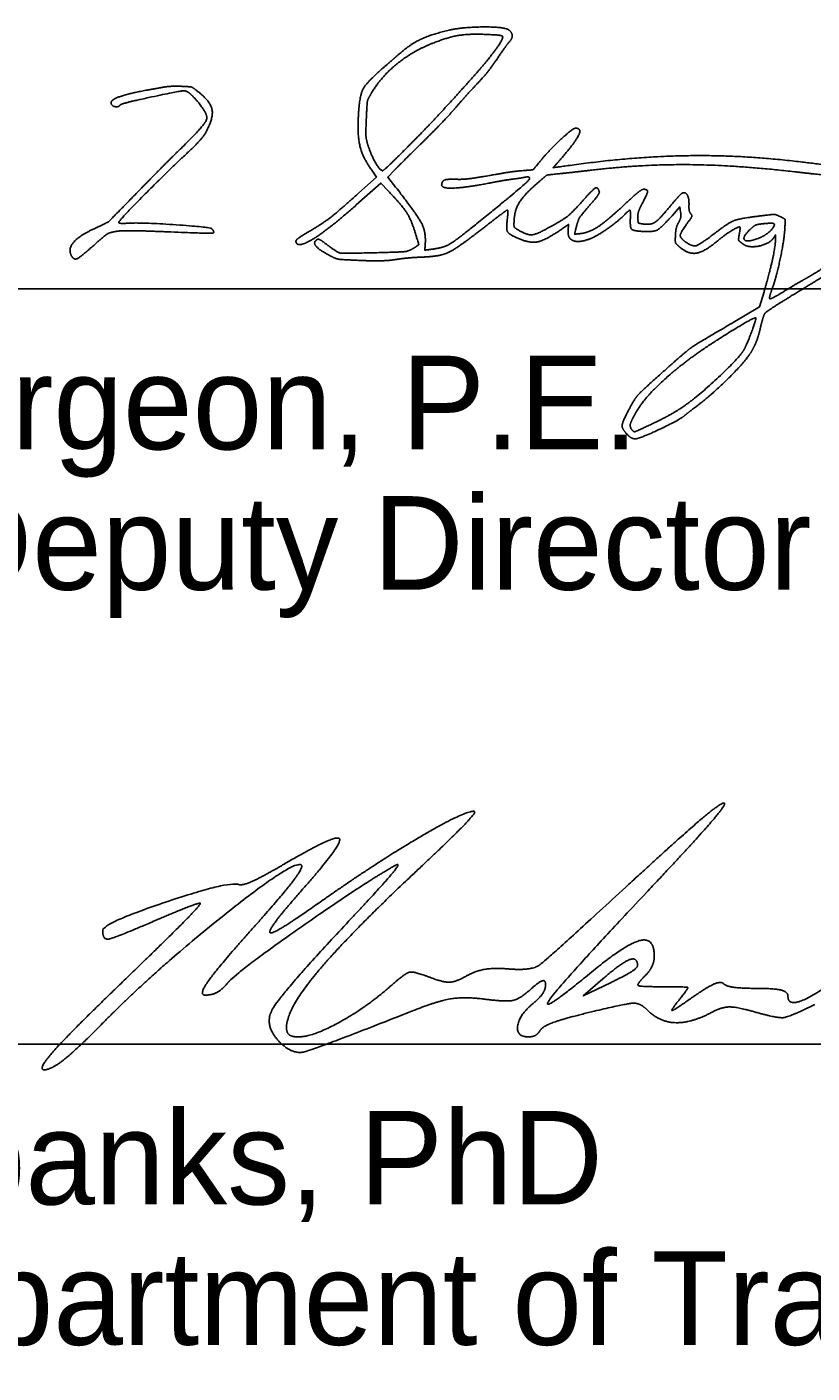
# Model space of a CAD drawing. Extents: x 0 to 34, y 0 to 22.
# Drawn here: x 25.89 to 27.065, y 8.24 to 10.253 of the extents above; entities that cross this region are included whole.
import ezdxf

# ---------------------------------------------------------------- set-up
doc = ezdxf.new("R2010")
doc.units = 0
doc.layers.add('SH_Data', color=7, linetype='Continuous')
doc.layers.add('SH_Text', color=7, linetype='Continuous')

msp = doc.modelspace()

# ---------------------------------------------------------------- linework, layer by layer
at = {"layer": 'SH_Data'}
for p, q in [((24.827, 9.8614), (28.327, 9.8614)), ((24.827, 8.7319), (28.327, 8.7319))]:
    msp.add_line(p, q, dxfattribs=at)
for points in [[(26.3868, 10.0049), (26.4132, 10.0286), (26.4051, 10.0404)], [(26.4402, 10.0391), (26.4301, 10.0287), (26.4419, 10.0136)], [(26.4309, 10.008), (26.4199, 10.0196), (26.383, 9.9869)], [(26.8681, 9.9761), (26.8668, 9.984), (26.8552, 9.9709)], [(26.7, 9.949), (26.7004, 9.9578), (26.6915, 9.9516)], [(26.9468, 9.8113), (26.986, 9.8344), (26.9928, 9.8572)]]:
    msp.add_lwpolyline(points, dxfattribs=at)
for points in [[(26.5221, 10.2484), (26.5433, 10.2532), (26.6063, 10.2532), (26.6116, 10.2484)], [(26.4976, 10.229), (26.4676, 10.2172), (26.4197, 10.1784), (26.4059, 10.1546)], [(26.4452, 10.2111), (26.4628, 10.2267), (26.4945, 10.2421), (26.5221, 10.2484)], [(26.5782, 10.242), (26.5523, 10.2431), (26.5204, 10.238), (26.4976, 10.229)], [(26.5644, 10.1861), (26.5811, 10.2051), (26.6018, 10.2335), (26.602, 10.2378)], [(26.602, 10.2378), (26.6021, 10.24), (26.5948, 10.2412), (26.5782, 10.242)], [(26.6113, 10.2302), (26.6093, 10.228), (26.6015, 10.2171), (26.594, 10.2059)], [(26.6116, 10.2484), (26.6164, 10.2442), (26.6162, 10.2355), (26.6113, 10.2302)], [(26.4267, 10.1951), (26.4344, 10.2017), (26.4427, 10.2089), (26.4452, 10.2111)], [(26.3859, 10.1149), (26.3874, 10.1493), (26.3984, 10.1708), (26.4267, 10.1951)], [(26.594, 10.2059), (26.5865, 10.1948), (26.5727, 10.1776), (26.5634, 10.1678)], [(26.4538, 10.0677), (26.4812, 10.095), (26.5305, 10.1478), (26.5644, 10.1861)], [(26.0189, 10.1439), (26.0229, 10.1474), (26.0492, 10.1549), (26.0705, 10.1588)], [(26.1436, 10.144), (26.1316, 10.1579), (26.1199, 10.1579), (26.0572, 10.1442)], [(26.0705, 10.1588), (26.0778, 10.1601), (26.0886, 10.162), (26.0944, 10.1631)], [(26.0944, 10.1631), (26.1003, 10.1641), (26.1123, 10.1647), (26.1211, 10.1644)], [(26.1211, 10.1644), (26.1347, 10.1639), (26.1386, 10.1626), (26.1474, 10.1556)], [(26.1474, 10.1556), (26.1656, 10.1412), (26.1694, 10.1158), (26.1568, 10.0935)], [(26.4059, 10.1546), (26.4001, 10.1447), (26.3991, 10.1394), (26.398, 10.1154)], [(26.5634, 10.1678), (26.5541, 10.1579), (26.5391, 10.1413), (26.5301, 10.1308)], [(26.0168, 10.1377), (26.0159, 10.1393), (26.0168, 10.1421), (26.0189, 10.1439)], [(26.0298, 10.1364), (26.0277, 10.1333), (26.0187, 10.1343), (26.0168, 10.1377)], [(26.0572, 10.1442), (26.0429, 10.141), (26.0305, 10.1375), (26.0298, 10.1364)], [(26.1209, 10.0716), (26.1567, 10.1066), (26.1618, 10.1228), (26.1436, 10.144)], [(26.5301, 10.1308), (26.5211, 10.1204), (26.4994, 10.0978), (26.482, 10.0806)], [(26.4051, 10.0404), (26.3928, 10.058), (26.3848, 10.0891), (26.3859, 10.1149)], [(26.398, 10.1154), (26.3971, 10.0948), (26.3979, 10.0843), (26.4011, 10.0744)], [(26.1568, 10.0935), (26.1542, 10.0891), (26.142, 10.0758), (26.1295, 10.0641)], [(26.6598, 10.0545), (26.6714, 10.0688), (26.7074, 10.102), (26.7111, 10.1019)], [(26.7111, 10.1019), (26.7202, 10.1015), (26.7119, 10.0828), (26.6925, 10.0599)], [(26.0576, 10.0079), (26.0779, 10.0288), (26.1064, 10.0574), (26.1209, 10.0716)], [(26.4011, 10.0744), (26.4055, 10.0611), (26.4188, 10.0383), (26.4222, 10.0381)], [(26.482, 10.0806), (26.4645, 10.0635), (26.4457, 10.0448), (26.4402, 10.0391)], [(26.1295, 10.0641), (26.0929, 10.0295), (26.0267, 9.9622), (26.0277, 9.9604)], [(26.4222, 10.0381), (26.4233, 10.0381), (26.4375, 10.0514), (26.4538, 10.0677)], [(26.6308, 10.0382), (26.6465, 10.0393), (26.6482, 10.0402), (26.6598, 10.0545)], [(26.6925, 10.0599), (26.6777, 10.0424), (26.6769, 10.0427), (26.7228, 10.0488)], [(26.7228, 10.0488), (26.8442, 10.065), (27.0678, 10.0536), (27.2246, 10.0231)], [(26.5344, 10.0253), (26.5416, 10.025), (26.5628, 10.0275), (26.5816, 10.0309)], [(26.5632, 9.959), (26.6278, 10.0111), (26.6485, 10.0315), (26.633, 10.028)], [(26.5816, 10.0309), (26.6003, 10.0343), (26.6224, 10.0376), (26.6308, 10.0382)], [(26.633, 10.028), (26.6304, 10.0274), (26.6236, 10.0264), (26.6177, 10.0257)], [(26.6905, 10.0341), (26.6685, 10.0318), (26.6678, 10.0315), (26.6519, 10.0178)], [(26.7355, 10.0391), (26.7231, 10.0376), (26.7029, 10.0354), (26.6905, 10.0341)], [(27.0382, 10.0366), (26.9505, 10.0467), (26.8098, 10.0478), (26.7355, 10.0391)], [(27.1274, 10.027), (27.1108, 10.0286), (27.0707, 10.0329), (27.0382, 10.0366)], [(25.9931, 9.9524), (26.0108, 9.9605), (26.0144, 9.9636), (26.0576, 10.0079)], [(26.4711, 9.9456), (26.4655, 9.9643), (26.4514, 9.9862), (26.4309, 10.008)], [(26.4419, 10.0136), (26.474, 9.9724), (26.4875, 9.9464), (26.4861, 9.9279)], [(26.5107, 10.017), (26.511, 10.0229), (26.5198, 10.0259), (26.5344, 10.0253)], [(26.5806, 10.0194), (26.5453, 10.0127), (26.5105, 10.0115), (26.5107, 10.017)], [(26.6177, 10.0257), (26.6119, 10.025), (26.5952, 10.0222), (26.5806, 10.0194)], [(26.6519, 10.0178), (26.6337, 10.002), (26.6196, 9.9786), (26.619, 9.9631)], [(26.7235, 9.9952), (26.7366, 10.0103), (26.7443, 10.0141), (26.7465, 10.0066)], [(26.7873, 9.9904), (26.7993, 10.0016), (26.8107, 10.0106), (26.8126, 10.0105)], [(26.8126, 10.0105), (26.8189, 10.0103), (26.8184, 10.0037), (26.811, 9.9898)], [(26.3097, 9.9456), (26.3332, 9.9595), (26.3544, 9.9758), (26.3868, 10.0049)], [(26.6692, 9.952), (26.6917, 9.9642), (26.7075, 9.9769), (26.7235, 9.9952)], [(26.733, 9.9874), (26.7186, 9.9709), (26.7147, 9.9643), (26.7113, 9.9507)], [(26.7193, 9.9443), (26.7318, 9.9457), (26.7589, 9.9641), (26.7873, 9.9904)], [(26.7465, 10.0066), (26.7469, 10.005), (26.7409, 9.9964), (26.733, 9.9874)], [(26.811, 9.9898), (26.8066, 9.9817), (26.8038, 9.9728), (26.804, 9.9678)], [(26.8537, 9.9864), (26.8617, 9.9962), (26.8696, 10.0045), (26.8711, 10.005)], [(26.8711, 10.005), (26.8758, 10.0063), (26.8809, 9.9963), (26.8806, 9.9864)], [(26.383, 9.9869), (26.349, 9.9569), (26.3064, 9.9273), (26.2976, 9.9277)], [(26.6086, 9.9793), (26.6076, 9.979), (26.5894, 9.9652), (26.5682, 9.9488)], [(26.622, 9.9383), (26.6106, 9.9436), (26.6072, 9.9512), (26.609, 9.967)], [(26.609, 9.967), (26.6098, 9.9741), (26.6096, 9.9796), (26.6086, 9.9793)], [(26.7837, 9.9719), (26.7743, 9.9623), (26.7418, 9.9397), (26.7324, 9.9362)], [(26.7929, 9.9668), (26.7934, 9.9785), (26.7913, 9.9797), (26.7837, 9.9719)], [(26.804, 9.9678), (26.8044, 9.9607), (26.8056, 9.9594), (26.8124, 9.9584)], [(26.8124, 9.9584), (26.8236, 9.9568), (26.8364, 9.9655), (26.8537, 9.9864)], [(26.8552, 9.9709), (26.8389, 9.9526), (26.8283, 9.9466), (26.8129, 9.9473)], [(26.8651, 9.9608), (26.8676, 9.9652), (26.8688, 9.9713), (26.8681, 9.9761)], [(26.8832, 9.9738), (26.8854, 9.9714), (26.8844, 9.9683), (26.8791, 9.961)], [(26.8806, 9.9864), (26.8804, 9.9812), (26.8816, 9.9756), (26.8832, 9.9738)], [(26.9236, 9.9479), (26.9404, 9.9608), (26.9565, 9.9667), (26.9852, 9.9703)], [(26.9852, 9.9703), (27.0054, 9.9729), (27.0104, 9.9728), (27.0169, 9.9696)], [(27.0169, 9.9696), (27.024, 9.9661), (27.0246, 9.9647), (27.024, 9.9526)], [(25.957, 9.911), (25.9514, 9.9211), (25.9692, 9.9415), (25.9931, 9.9524)], [(26.0231, 9.9473), (26.0137, 9.9456), (26.0069, 9.9413), (25.9903, 9.9265)], [(26.1, 9.9468), (26.0643, 9.9483), (26.0297, 9.9486), (26.0231, 9.9473)], [(26.0277, 9.9604), (26.0282, 9.9596), (26.0349, 9.9592), (26.0426, 9.9597)], [(26.0426, 9.9597), (26.0606, 9.9608), (26.1646, 9.9538), (26.1669, 9.9513)], [(26.1669, 9.9513), (26.1727, 9.9449), (26.1614, 9.9442), (26.1, 9.9468)], [(26.4954, 9.9206), (26.5132, 9.9229), (26.5311, 9.9331), (26.5632, 9.959)], [(26.5682, 9.9488), (26.546, 9.9316), (26.5242, 9.917), (26.5171, 9.9144)], [(26.619, 9.9631), (26.6186, 9.9549), (26.6198, 9.9526), (26.6261, 9.949)], [(26.6915, 9.9516), (26.6663, 9.9341), (26.6411, 9.9293), (26.622, 9.9383)], [(26.6261, 9.949), (26.6386, 9.9418), (26.6522, 9.9427), (26.6692, 9.952)], [(26.7026, 9.9369), (26.7009, 9.9387), (26.6998, 9.9441), (26.7, 9.949)], [(26.7113, 9.9507), (26.7095, 9.9432), (26.7096, 9.9431), (26.7193, 9.9443)], [(26.8129, 9.9473), (26.7974, 9.948), (26.7923, 9.9529), (26.7929, 9.9668)], [(26.8603, 9.9416), (26.8606, 9.9481), (26.8627, 9.9567), (26.8651, 9.9608)], [(26.8791, 9.961), (26.8684, 9.9462), (26.8668, 9.9382), (26.8737, 9.933)], [(26.8737, 9.933), (26.8851, 9.9242), (26.8978, 9.928), (26.9236, 9.9479)], [(26.956, 9.9542), (26.9534, 9.9543), (26.9337, 9.9419), (26.9258, 9.9352)], [(26.956, 9.9441), (26.957, 9.9496), (26.957, 9.9542), (26.956, 9.9542)], [(26.9725, 9.9507), (26.9593, 9.9381), (26.9688, 9.9305), (26.9877, 9.9385)], [(26.9932, 9.959), (26.9835, 9.9581), (26.9779, 9.9559), (26.9725, 9.9507)], [(26.9877, 9.9385), (26.9962, 9.942), (27.0101, 9.9563), (27.0077, 9.9589)], [(27.0077, 9.9589), (27.0071, 9.9596), (27.0006, 9.9597), (26.9932, 9.959)], [(27.024, 9.9526), (27.0233, 9.9367), (27.0119, 9.8811), (27.0057, 9.8635)], [(26.2929, 9.9314), (26.2921, 9.9337), (26.2983, 9.939), (26.3097, 9.9456)], [(26.2976, 9.9277), (26.2957, 9.9278), (26.2935, 9.9295), (26.2929, 9.9314)], [(26.3441, 9.9108), (26.327, 9.9198), (26.3179, 9.9315), (26.325, 9.9355)], [(26.325, 9.9355), (26.3263, 9.9362), (26.3318, 9.9332), (26.3373, 9.929)], [(26.3373, 9.929), (26.3539, 9.916), (26.3628, 9.9143), (26.4072, 9.9154)], [(26.4712, 9.9238), (26.4765, 9.9274), (26.4765, 9.9276), (26.4711, 9.9456)], [(26.4861, 9.9279), (26.4855, 9.9193), (26.4856, 9.9193), (26.4954, 9.9206)], [(26.7324, 9.9362), (26.7211, 9.9321), (26.7067, 9.9324), (26.7026, 9.9369)], [(26.8665, 9.9241), (26.861, 9.9288), (26.8599, 9.932), (26.8603, 9.9416)], [(26.9258, 9.9352), (26.9049, 9.9173), (26.8799, 9.9126), (26.8665, 9.9241)], [(26.9601, 9.9294), (26.9551, 9.9332), (26.9545, 9.9356), (26.956, 9.9441)], [(26.974, 9.9245), (26.9696, 9.9247), (26.9634, 9.9269), (26.9601, 9.9294)], [(27.0073, 9.9379), (27.0034, 9.9318), (26.9843, 9.9242), (26.974, 9.9245)], [(26.9928, 9.8572), (27.0008, 9.884), (27.0096, 9.9236), (27.01, 9.9348)], [(27.01, 9.9348), (27.0102, 9.9416), (27.0099, 9.942), (27.0073, 9.9379)], [(25.9903, 9.9265), (25.9704, 9.9088), (25.9607, 9.9043), (25.957, 9.911)], [(26.3886, 9.904), (26.3607, 9.9052), (26.3525, 9.9064), (26.3441, 9.9108)], [(26.4072, 9.9154), (26.4497, 9.9164), (26.4627, 9.9181), (26.4712, 9.9238)], [(26.4823, 9.909), (26.47, 9.9085), (26.4515, 9.9068), (26.4413, 9.9052)], [(26.5171, 9.9144), (26.5103, 9.9119), (26.4946, 9.9095), (26.4823, 9.909)], [(27.0572, 9.8779), (27.0688, 9.8843), (27.0982, 9.9041), (27.1104, 9.9137)], [(26.4413, 9.9052), (26.4311, 9.9037), (26.4074, 9.9031), (26.3886, 9.904)], [(27.1051, 9.896), (27.0967, 9.8899), (27.0688, 9.8722), (27.043, 9.8566)], [(27.0218, 9.8571), (27.0334, 9.8642), (27.0493, 9.8736), (27.0572, 9.8779)], [(27.043, 9.8566), (27.0173, 9.8409), (26.9952, 9.8265), (26.994, 9.8246)], [(27.0057, 9.8635), (27.0032, 9.8566), (27.0011, 9.8494), (27.001, 9.8475)], [(27.001, 9.8475), (27.001, 9.8457), (27.0103, 9.85), (27.0218, 9.8571)], [(26.8427, 9.7381), (26.8782, 9.7697), (26.8889, 9.7772), (26.9468, 9.8113)], [(26.9803, 9.8181), (26.979, 9.8196), (26.9178, 9.7824), (26.8947, 9.7662)], [(26.9624, 9.7696), (26.9669, 9.7772), (26.9815, 9.8168), (26.9803, 9.8181)], [(26.994, 9.8246), (26.9927, 9.8226), (26.9897, 9.8125), (26.9872, 9.802)], [(26.9872, 9.802), (26.9847, 9.7915), (26.9791, 9.7766), (26.9747, 9.7689)], [(26.8947, 9.7662), (26.8607, 9.7422), (26.8119, 9.6956), (26.8017, 9.6773)], [(26.8715, 9.6849), (26.8907, 9.6976), (26.9553, 9.7578), (26.9624, 9.7696)], [(26.9747, 9.7689), (26.9666, 9.7547), (26.9157, 9.7038), (26.8903, 9.6845)], [(26.7881, 9.6759), (26.7983, 9.6959), (26.8096, 9.7087), (26.8427, 9.7381)], [(26.7879, 9.6441), (26.7804, 9.6523), (26.7805, 9.6609), (26.7881, 9.6759)], [(26.8017, 9.6773), (26.7968, 9.6685), (26.7927, 9.6597), (26.7926, 9.6578)], [(26.8736, 9.6715), (26.866, 9.6651), (26.8055, 9.6369), (26.7999, 9.6371)], [(26.8265, 9.66), (26.8408, 9.6668), (26.861, 9.678), (26.8715, 9.6849)], [(26.8903, 9.6845), (26.8831, 9.6791), (26.8756, 9.6732), (26.8736, 9.6715)], [(26.7926, 9.6578), (26.7925, 9.6546), (26.7971, 9.6478), (26.7995, 9.6477)], [(26.7995, 9.6477), (26.8, 9.6477), (26.8121, 9.6532), (26.8265, 9.66)], [(26.7999, 9.6371), (26.7967, 9.6373), (26.7913, 9.6404), (26.7879, 9.6441)]]:
    msp.add_open_spline(points, degree=2, dxfattribs=at)
at = {"layer": 'SH_Text'}
for p, q in [((26.8036, 8.8491), (26.8036, 8.8491)), ((26.0265, 8.8181), (26.0265, 8.8181))]:
    msp.add_line(p, q, dxfattribs=at)
msp.add_lwpolyline([(26.7519, 8.8294), (26.7224, 8.8038), (26.763, 8.8235)], dxfattribs=at)
for points in [[(26.786, 8.9666), (26.861, 9.0357), (26.927, 9.0923), (26.9328, 9.0924)], [(26.9328, 9.0924), (26.9385, 9.0925), (26.8865, 9.0323), (26.8171, 8.9587)], [(26.3317, 8.9462), (26.4123, 9.0028), (26.5436, 9.0801), (26.5593, 9.0801)], [(26.5593, 9.0801), (26.5642, 9.0801), (26.5229, 9.0374), (26.4675, 8.9854)], [(26.2728, 8.9997), (26.3515, 9.0459), (26.3638, 9.0326), (26.3045, 8.9653)], [(26.3009, 8.9995), (26.2912, 9.0091), (26.0815, 8.8422), (26.0036, 8.7629)], [(26.4411, 8.999), (26.3921, 8.9712), (26.2037, 8.839), (26.1905, 8.8231)], [(26.2071, 8.9705), (26.2127, 8.9687), (26.2422, 8.9818), (26.2728, 8.9997)], [(26.223, 8.8991), (26.2693, 8.9508), (26.3043, 8.996), (26.3009, 8.9995)], [(26.4675, 8.9854), (26.3679, 8.8916), (26.2786, 8.7835), (26.2786, 8.7565)], [(26.3759, 8.9201), (26.4221, 8.9693), (26.4514, 9.0049), (26.4411, 8.999)], [(26.0038, 8.9019), (26.004, 8.9125), (26.1914, 8.9757), (26.2071, 8.9705)], [(26.3045, 8.9653), (26.2765, 8.9335), (26.2536, 8.9038), (26.2536, 8.8994)], [(26.611, 8.8442), (26.6445, 8.8414), (26.668, 8.8578), (26.786, 8.9666)], [(26.0265, 8.8181), (26.0975, 8.8865), (26.1528, 8.9426), (26.1494, 8.9426)], [(26.1494, 8.9426), (26.146, 8.9426), (26.1169, 8.9313), (26.0849, 8.9176)], [(26.2536, 8.8994), (26.2536, 8.8949), (26.2888, 8.916), (26.3317, 8.9462)], [(26.8171, 8.9587), (26.6876, 8.8212), (26.6555, 8.7739), (26.7377, 8.8417)], [(26.2688, 8.7345), (26.2436, 8.7597), (26.2725, 8.8098), (26.3759, 8.9201)], [(26.0849, 8.9176), (26.0223, 8.8907), (26.0035, 8.8871), (26.0038, 8.9019)], [(27.0286, 8.8036), (27.0286, 8.7807), (27.1239, 8.8422), (27.1942, 8.9104)], [(26.1572, 8.8051), (26.1469, 8.8051), (26.1758, 8.8463), (26.223, 8.8991)], [(26.7377, 8.8417), (26.7861, 8.8816), (26.8286, 8.8919), (26.8286, 8.8638)], [(26.8286, 8.8638), (26.8286, 8.8549), (26.8219, 8.8408), (26.8136, 8.8326)], [(26.4361, 8.8201), (26.4564, 8.8381), (26.4693, 8.8407), (26.493, 8.8317)], [(26.548, 8.8338), (26.5614, 8.8413), (26.5897, 8.846), (26.611, 8.8442)], [(26.8036, 8.8491), (26.8036, 8.8626), (26.7795, 8.8534), (26.7519, 8.8294)], [(26.763, 8.8235), (26.7853, 8.8343), (26.8036, 8.8459), (26.8036, 8.8491)], [(26.1905, 8.8231), (26.1823, 8.8132), (26.1673, 8.8051), (26.1572, 8.8051)], [(26.2966, 8.7426), (26.3184, 8.7426), (26.3997, 8.7878), (26.4361, 8.8201)], [(26.493, 8.8317), (26.5132, 8.824), (26.532, 8.8247), (26.548, 8.8338)], [(26.6661, 8.821), (26.6661, 8.8281), (26.6559, 8.8247), (26.6435, 8.8135)], [(26.6474, 8.7926), (26.6577, 8.8011), (26.6661, 8.8139), (26.6661, 8.821)], [(26.8136, 8.8326), (26.8019, 8.8209), (26.8078, 8.8176), (26.8401, 8.8176)], [(26.8863, 8.8021), (26.9077, 8.8171), (26.9284, 8.8261), (26.9323, 8.8222)], [(26.9323, 8.8222), (26.9362, 8.8183), (26.9595, 8.8151), (26.984, 8.8151)], [(25.9161, 8.6933), (25.9058, 8.6935), (25.9555, 8.7496), (26.0265, 8.8181)], [(26.574, 8.7991), (26.5448, 8.8028), (26.505, 8.7964), (26.4685, 8.782)], [(26.6435, 8.8135), (26.6279, 8.7993), (26.6066, 8.7949), (26.574, 8.7991)], [(26.8401, 8.8176), (26.8777, 8.8176), (26.88, 8.8155), (26.8645, 8.7962)], [(26.8645, 8.7962), (26.8525, 8.7812), (26.859, 8.7829), (26.8863, 8.8021)], [(26.984, 8.8151), (27.0085, 8.8151), (27.0286, 8.8099), (27.0286, 8.8036)], [(26.4685, 8.782), (26.3224, 8.7243), (26.2874, 8.7159), (26.2688, 8.7345)], [(26.6404, 8.7426), (26.622, 8.7426), (26.6266, 8.7753), (26.6474, 8.7926)], [(26.7347, 8.78), (26.6963, 8.7708), (26.6621, 8.7586), (26.6585, 8.7529)], [(26.819, 8.7822), (26.8079, 8.7933), (26.7878, 8.7928), (26.7347, 8.78)], [(26.9153, 8.7796), (26.8846, 8.7632), (26.8367, 8.7644), (26.819, 8.7822)], [(26.9798, 8.7797), (26.9529, 8.7874), (26.9298, 8.7874), (26.9153, 8.7796)], [(27.0689, 8.7911), (27.0315, 8.7726), (27.013, 8.7702), (26.9798, 8.7797)], [(26.0036, 8.7629), (25.9658, 8.7244), (25.9264, 8.6931), (25.9161, 8.6933)], [(26.2786, 8.7565), (26.2786, 8.7488), (26.2867, 8.7426), (26.2966, 8.7426)], [(26.6585, 8.7529), (26.655, 8.7472), (26.6468, 8.7426), (26.6404, 8.7426)]]:
    msp.add_open_spline(points, degree=2, dxfattribs=at)

# ---------------------------------------------------------------- texts
for s, p in [('Jason L. Sturgeon, P.E.', (24.827, 9.6214)), ('District       Deputy Director', (24.827, 9.4114)), ('Jack Marchbanks, PhD', (24.827, 8.4919)), ('Director, Department of Transportation', (24.827, 8.2819))]:
    msp.add_text(s, height=0.14, dxfattribs=at).set_placement(p)

doc.saveas('drawing.dxf')
